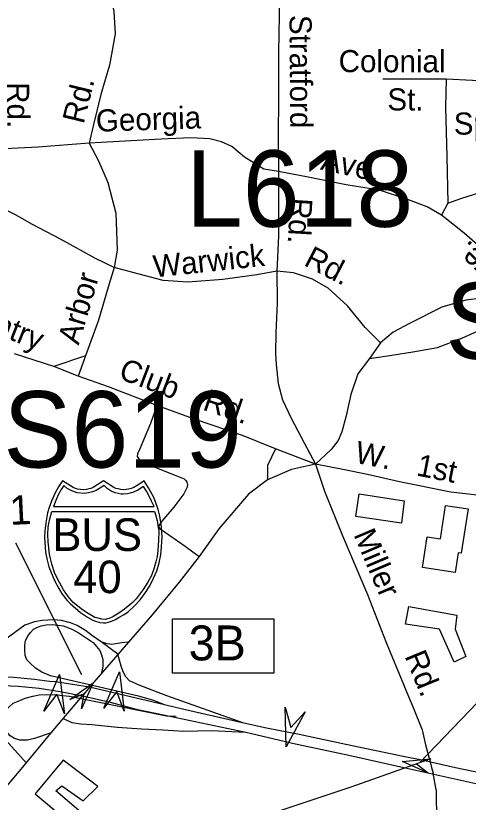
# Model space of a CAD drawing. Extents: x 1547597 to 1699558, y 810033 to 920809.
# Drawn here: x 1621816 to 1623759, y 855063 to 858442 of the extents above; entities that cross this region are included whole.
import ezdxf

# ---------------------------------------------------------------- set-up
doc = ezdxf.new("R2010")
doc.units = 0
for name, color, linetype in [('Exist Cultural Warehouse Building Footprint', 7, 'Continuous'), ('Exist Railroad Mainline', 7, 'Continuous'), ('Exist Road Non-System Type 51', 7, 'Continuous'), ('Exist Road Non-System Type 51 Label', 7, 'Continuous'), ('Exist Road Primary Interstate Divided Center Attributed', 7, 'Continuous'), ('Exist Road Primary Interstate Interchange CELL', 7, 'Continuous'), ('Exist Road Primary Interstate Ramp 1 Lane Attributed', 7, 'Continuous'), ('Exist Road Primary Interstate Shield CELL', 7, 'Continuous'), ('Exist Road Primary Interstate Shield Number Label', 7, 'Continuous'), ('Exist Road Primary Interstate Structure Cantilever Sign Attributed CELL', 7, 'Continuous'), ('Exist Road Primary Interstate Structure Cantilever Sign Number Label', 7, 'Continuous'), ('Exist Road Primary Interstate Structure Ovrhead Sign Attributed CELL', 7, 'Continuous'), ('Exist Road Primary Interstate Structure Ovrhead Sign Number Label', 7, 'Continuous'), ('Exist Road Primary US Mileage Hundredths English Label', 7, 'Continuous'), ('Exist Road Primary US UnDivided 4 Lane Attributed', 7, 'Continuous'), ('Exist Road Secondary Structure Standard Bridge Attributed CELL', 7, 'Continuous')]:
    doc.layers.add(name, color=color, linetype=linetype)

msp = doc.modelspace()

# ---------------------------------------------------------------- linework, layer by layer
at = {"layer": 'Exist Cultural Warehouse Building Footprint'}
for points in [[(1623291.3, 856387.8), (1623484.1, 856357.9), (1623472.5, 856261.4), (1623276.3, 856291.3)], [(1623562.8, 856071.5), (1623583, 856203), (1623640, 856194.3), (1623662.2, 856338.6), (1623758.4, 856323.8), (1623729.1, 856133.1), (1623716.3, 856135.1), (1623703.2, 856049.9)], [(1623504.1, 855903.6), (1623710.3, 855867), (1623703.6, 855807.1), (1623748.5, 855688.9), (1623698.6, 855665.6), (1623635.4, 855807.1), (1623489.1, 855828.7)], [(1622020.2, 855244.5), (1621899, 855099), (1622060.6, 854964.2), (1622106.4, 855012.7), (1621987.9, 855112.4), (1622014.8, 855134), (1622106.4, 855069.3), (1622168.4, 855131.3)]]:
    msp.add_lwpolyline(points, close=True, dxfattribs=at)
at = {"layer": 'Exist Railroad Mainline'}
msp.add_lwpolyline([(1620826, 854318.2), (1621032.6, 854389.6), (1621343.6, 854489.6), (1621650.5, 854595.6), (1621961.6, 854699.6), (1622242.6, 854798.1), (1622615.9, 854910.1), (1622951.9, 855027.5), (1623255.9, 855128.9), (1623550.6, 855233.7), (1623868.5, 855565)], dxfattribs=at)
at = {"layer": 'Exist Road Non-System Type 51'}
for p, q in [((1623664.2, 858169), (1623392.5, 858169.5)), ((1623671.5, 857637.1), (1623644.6, 857585.6)), ((1623381.7, 857036.3), (1623334.7, 856969)), ((1621979.5, 856935.1), (1621810.7, 856989.7)), ((1622115.7, 856981.1), (1621979.5, 856935.1)), ((1622115.7, 856981.1), (1622084.7, 856893.3)), ((1622084.7, 856893.3), (1621979.5, 856935.1)), ((1623103.4, 856515), (1622930.9, 856581.8)), ((1623576.2, 855309.2), (1623595.4, 855236.4)), ((1623595.4, 855236.4), (1623601.9, 855212.1)), ((1623601.9, 855212.1), (1623608.7, 855187.8)), ((1623621.7, 855116.1), (1623608.7, 855187.8))]:
    msp.add_line(p, q, dxfattribs=at)
for points in [[(1622050.9, 858904.9), (1622070.8, 858831.1), (1622127.5, 858744.3), (1622187.6, 858631.4), (1622218.4, 858550.9), (1622237, 858460.7), (1622243.6, 858364.7), (1622219.5, 858229.1), (1622181.7, 858103.8), (1622149.7, 857974.4), (1622131.5, 857894.3)], [(1622949.2, 858914.3), (1622948.7, 858762.2), (1622948.9, 858526.5), (1622944.8, 858284.6), (1622943.8, 858096.7), (1622942.8, 857918.9), (1622944.4, 857772.9)], [(1623664.2, 858169), (1623662.2, 858049.2), (1623666.7, 857837.1), (1623671.5, 857637.1)], [(1623871.7, 858157.6), (1623778, 858163.1), (1623664.2, 858169)], [(1622131.5, 857894.3), (1621912.6, 857877.9), (1621739.5, 857868.2)], [(1622944.4, 857772.9), (1622882, 857783.4), (1622799, 857834.7), (1622743.7, 857879.5), (1622700.1, 857900.2), (1622650.3, 857913), (1622568.4, 857918.1), (1622440.6, 857912), (1622286.5, 857902.4), (1622131.5, 857894.3)], [(1622131.5, 857894.3), (1622171.3, 857818.1), (1622211.9, 857725.6), (1622245.8, 857593.2), (1622251.4, 857435.2), (1622239.3, 857361)], [(1622944.4, 857772.9), (1622945, 857682.9), (1622943.8, 857497), (1622937.3, 857345.3)], [(1623644.6, 857585.6), (1623583.3, 857620.5), (1623491.9, 857656), (1623378.6, 857691.9), (1623235.2, 857716.2), (1623071.8, 857748.8), (1622944.4, 857772.9)], [(1623671.5, 857637.1), (1623731.7, 857658.1), (1623882.4, 857705.7), (1624040.7, 857737.1), (1624172.8, 857750.8), (1624268.7, 857753.3), (1624390.5, 857749.4), (1624568.2, 857736.4), (1624805.6, 857724.6), (1624991.1, 857701.6)], [(1622239.3, 857361), (1622159, 857398.7), (1622008.4, 857482.8), (1621885.5, 857546.5), (1621818.2, 857585.5), (1621723.9, 857630.6)], [(1623956.4, 857232.7), (1623931.6, 857303.1), (1623865.1, 857388.1), (1623798.3, 857457.3), (1623741.3, 857508), (1623644.6, 857585.6)], [(1622239.3, 857361), (1622213.2, 857275.9), (1622171.1, 857134.5), (1622115.7, 856981.1)], [(1622937.3, 857345.3), (1622851.2, 857328.2), (1622705.1, 857308.5), (1622555, 857296.8), (1622449.3, 857304.3), (1622345.8, 857331.8), (1622239.3, 857361)], [(1622937.3, 857345.3), (1622939.2, 857207.3), (1622933, 857081.4), (1622931.6, 856991.6), (1622934.8, 856943.5), (1622943.3, 856861.5), (1622962.1, 856791.2), (1622999, 856712.7), (1623055.1, 856607.7), (1623103.4, 856515)], [(1623381.7, 857036.3), (1623317, 857103.2), (1623240.5, 857196.4), (1623158, 857271.7), (1623090.5, 857310.7), (1623009.2, 857338), (1622937.3, 857345.3)], [(1623956.4, 857232.7), (1623854.6, 857232.4), (1623748.4, 857220.1), (1623646, 857189.8), (1623507.1, 857120.2), (1623436.5, 857083.2), (1623381.7, 857036.3)], [(1623334.7, 856969), (1623430.9, 856983.4), (1623521, 856998), (1623627.2, 857016.3), (1623731.7, 857056.4), (1623812.3, 857093.2), (1623892.4, 857103.8), (1623968.3, 857100.6)], [(1623334.7, 856969), (1623285.8, 856903.7), (1623254.4, 856814.3), (1623234.7, 856722.7), (1623215.7, 856655), (1623201.1, 856617.3), (1623170.5, 856577.9), (1623103.4, 856515)], [(1622422.4, 856768), (1622213.9, 856847.2), (1622084.7, 856893.3)], [(1622422.4, 856768), (1622394.6, 856690.5), (1622348.7, 856581.4), (1622338.7, 856559.6), (1622337.3, 856548.8), (1622346.6, 856535.6), (1622377.9, 856516.9), (1622497.1, 856469.1), (1622538.8, 856452.6), (1622546.7, 856445.5), (1622550.6, 856438.4), (1622553.5, 856427.3), (1622552.3, 856416.3), (1622537.9, 856388.6), (1622495, 856331.3), (1622444.1, 856270.1), (1622431.9, 856253.9), (1622429.8, 856246.3), (1622434.3, 856239.8), (1622445.5, 856232), (1622544.4, 856162.6), (1622603.8, 856118.2)], [(1622930.9, 856581.8), (1622789.9, 856638.1), (1622583.3, 856709.3), (1622422.4, 856768)], [(1622930.9, 856581.8), (1622897.2, 856509.8), (1622897.2, 856448)], [(1623103.4, 856515), (1623000, 856493.3), (1622897.2, 856448)], [(1623948.2, 856365.4), (1623860.4, 856374.8), (1623684.9, 856395.6), (1623463.9, 856439.3), (1623326.6, 856471.5), (1623221, 856493), (1623103.4, 856515)], [(1623103.4, 856515), (1623141.5, 856399.6), (1623220.4, 856204.5), (1623326.6, 855955), (1623407.3, 855750), (1623482.9, 855566.3), (1623495.9, 855534.7), (1623522.2, 855470.2), (1623561.5, 855373.9), (1623576.2, 855309.2)], [(1622897.2, 856448), (1622815, 856386.3), (1622687.6, 856238.3), (1622603.8, 856118.2)], [(1622603.8, 856118.2), (1622517.3, 856008.2), (1622402.6, 855867.7), (1622132.4, 855557.4)], [(1623621.7, 855116.1), (1623623, 854978.3), (1623624.1, 854864.3), (1623627, 854549.7)]]:
    msp.add_lwpolyline(points, dxfattribs=at)
at = {"layer": 'Exist Road Primary Interstate Divided Center Attributed'}
for points in [[(1622132.4, 855557.4), (1621987.3, 855580.3), (1621960.5, 855582.2), (1621896.7, 855589.9), (1621808.5, 855598.5), (1621707.9, 855603.2), (1621647.1, 855603.2), (1621486.4, 855593.6), (1621344.4, 855579.5)], [(1621094.5, 855465.5), (1621166.7, 855490.4), (1621252.9, 855513.8), (1621365.3, 855539.8), (1621462.3, 855555.5), (1621537.3, 855561.1), (1621639.9, 855567.2), (1621727.6, 855565.8), (1621826, 855561.8), (1621916.9, 855552.9), (1622007.3, 855538.9), (1622102.8, 855519.9)], [(1622796.2, 855402.7), (1622532.6, 855463.7), (1622454.4, 855481), (1622132.4, 855557.4)], [(1622102.8, 855519.9), (1622221.4, 855492.6), (1622334, 855462.8), (1622450.9, 855439.4), (1622804.5, 855363.8)], [(1623560, 855243.5), (1623480.4, 855259.4), (1623233.1, 855310.6), (1623032.6, 855354.7), (1622892.8, 855382), (1622796.2, 855402.7)], [(1622804.5, 855363.8), (1622829, 855358.6), (1623018.1, 855314), (1623246.3, 855265.4), (1623483.3, 855212.3)], [(1624233.7, 855069.8), (1623946.4, 855160.9), (1623703.8, 855211.6), (1623560, 855243.5)], [(1623483.3, 855212.3), (1623830.2, 855134.7), (1623968.5, 855100.4)]]:
    msp.add_lwpolyline(points, dxfattribs=at)
at = {"layer": 'Exist Road Primary Interstate Interchange CELL'}
msp.add_lwpolyline([(1622489.2, 855851), (1622924.1, 855851), (1622924.1, 855617.7), (1622489.2, 855617.7)], close=True, dxfattribs=at)
at = {"layer": 'Exist Road Primary Interstate Ramp 1 Lane Attributed'}
msp.add_line((1622254.6, 855699.5), (1622183.1, 855752.6), dxfattribs=at)
for points in [[(1622183.1, 855752.6), (1622141.3, 855780.4), (1622116, 855800.8), (1622080.4, 855822.8), (1622051.8, 855834.1), (1622012.9, 855844.4), (1621978.3, 855847.3), (1621930.3, 855844.6), (1621896.1, 855838.3), (1621855.7, 855824.3), (1621769.8, 855760.7), (1621691.6, 855697.6), (1621574, 855639), (1621508, 855616.5), (1621344.4, 855579.5)], [(1622454.4, 855481), (1622408.9, 855500.7), (1622343.3, 855518.9), (1621965.6, 855606.8), (1621928.1, 855622.3), (1621900.9, 855638.7), (1621876.6, 855662.6), (1621863.9, 855675.2), (1621856.9, 855693.5), (1621854.6, 855718.8), (1621854.6, 855738), (1621858.8, 855758.6), (1621868.6, 855777.1), (1621879.4, 855792.6), (1621892.5, 855806.7), (1621906.1, 855814.2), (1621925.3, 855821.2), (1621947.3, 855825.9), (1621974.5, 855827.3), (1621997.5, 855824.5), (1622020, 855820.7), (1622054.4, 855808.5), (1622084.4, 855792.8), (1622148.5, 855750), (1622177, 855715.7), (1622185.1, 855697.1), (1622189.9, 855675.8), (1622189.8, 855646.5), (1622184.2, 855618.7)], [(1622299.5, 855750.5), (1622272.3, 855748), (1622229.5, 855740.4), (1622208.5, 855744), (1622183.1, 855752.6)], [(1622796.2, 855402.7), (1622464.9, 855520.2), (1622346.3, 855565.8), (1622305, 855584.4), (1622289.3, 855602.2), (1622277.2, 855623.6), (1622268.7, 855647.9), (1622254.6, 855699.5)], [(1621094.5, 855465.5), (1621118.4, 855461.8), (1621178.4, 855478.2), (1621295.1, 855509.3), (1621384.1, 855524.8), (1621438.4, 855533.2), (1621489.5, 855536.5), (1621529.8, 855531.8), (1621566.8, 855525.3), (1621588.9, 855520.1), (1621610.9, 855510.7), (1621642.3, 855492.9), (1621719.3, 855390.2), (1621787.2, 855315.3), (1621862.1, 855230.4)], [(1621968.9, 855361), (1621897.1, 855336.4), (1621866.7, 855329.4), (1621834, 855329.4), (1621810.6, 855336.4), (1621791.9, 855348.1), (1621775.5, 855369.2), (1621766.1, 855392.6), (1621763.8, 855416), (1621766.1, 855439.4), (1621773.1, 855458.1), (1621787.2, 855472.1), (1621805.9, 855488.5), (1621834, 855500.2), (1621856.9, 855510.5), (1621890.2, 855519.4), (1621917.3, 855524.6), (1621948.6, 855526), (1621991.9, 855524.6), (1622047.6, 855518.5), (1622463.7, 855433.9), (1622505.4, 855432.5)], [(1622022.8, 855421.4), (1622057.1, 855405.8), (1622096, 855399.6), (1622142.7, 855397.3), (1622252.6, 855385.5), (1622355.6, 855378.5), (1622449.2, 855373.8), (1622538.1, 855369.2), (1622655.1, 855371.5), (1622804.5, 855363.8)]]:
    msp.add_lwpolyline(points, dxfattribs=at)
at = {"layer": 'Exist Road Primary Interstate Shield CELL'}
for points in [[(1622192.9, 855833.7), (1622202.4, 855834.6), (1622215.1, 855837.1), (1622227.5, 855841.2), (1622241.6, 855847.4), (1622262.5, 855859), (1622279.2, 855868.8), (1622298.6, 855881.8), (1622324.7, 855905.5), (1622350.7, 855932.9), (1622373.7, 855963.9), (1622392, 855992.9), (1622408, 856026.1), (1622421.5, 856057), (1622432.1, 856092.3), (1622439.2, 856126.6), (1622442.8, 856162.3), (1622445.1, 856201.8), (1622442.5, 856246.4), (1622434.7, 856291.9), (1622427.4, 856320.3), (1622416.4, 856354.2), (1622407.4, 856375.9), (1622386.6, 856414.3), (1622367.8, 856443.9), (1622340.6, 856424.8), (1622322.8, 856415.3), (1622312, 856410.5), (1622300.8, 856408.3), (1622280.3, 856405.8), (1622267.5, 856406.4), (1622255.5, 856409.1), (1622245.4, 856411.3), (1622237.1, 856415.3), (1622192.9, 856443.9), (1622148.6, 856415.3), (1622139.3, 856411.1), (1622129.8, 856409.1), (1622120.7, 856406.6), (1622105.6, 856405.8), (1622094, 856406.2), (1622082.1, 856408.3), (1622072.7, 856410.3), (1622062.2, 856415.3), (1622017.1, 856443.9), (1621999.4, 856418.2), (1621984.9, 856392.8), (1621969.6, 856356.9), (1621960, 856329.1), (1621953.2, 856306.2), (1621944.9, 856264.2), (1621940.5, 856227.7), (1621939.8, 856201.8), (1621944.5, 856137.3), (1621951.6, 856103), (1621958.8, 856075.2), (1621982.7, 856015.1), (1622000.6, 855981.5), (1622016, 855957.4), (1622037.6, 855930.2), (1622049.3, 855917.2), (1622094.1, 855878.1), (1622124, 855857.6), (1622147.9, 855844.7), (1622159.2, 855840.4), (1622176.7, 855835.5)], [(1622022.5, 856423.2), (1622011.5, 856406.3), (1621998.8, 856383.4), (1621988.7, 856359.8), (1621978.3, 856333.6), (1622409.9, 856333.5), (1622399.8, 856355.9), (1622389.1, 856378.4), (1622377.8, 856399), (1622364.1, 856418.9), (1622339.9, 856403.6), (1622322.3, 856395.3), (1622308.1, 856390.4), (1622296.1, 856387.7), (1622277.5, 856386.2), (1622269.2, 856386.7), (1622243.3, 856392.6), (1622225.7, 856399.8), (1622209, 856410.9), (1622195.5, 856423.6), (1622161.3, 856403), (1622146.1, 856396.3), (1622128.7, 856391.8), (1622109.6, 856389.4), (1622080.2, 856392.6), (1622057.1, 856400.6), (1622037.2, 856410.9)], [(1622412.4, 856312.2), (1622417, 856300), (1622423.4, 856272.9), (1622426.7, 856252.1), (1622430.2, 856228.1), (1622429, 856187), (1622427, 856144.4), (1622423.1, 856119.2), (1622417.8, 856096.2), (1622410.7, 856070.8), (1622399.2, 856036.9), (1622383.2, 856008.3), (1622363.4, 855976.5), (1622341.9, 855948.6), (1622332.6, 855937), (1622314.8, 855918.4), (1622282.6, 855892.5), (1622259.1, 855874.9), (1622230.9, 855858.3), (1622216.6, 855851.9), (1622200, 855848.4), (1622186.3, 855849.4), (1622169.6, 855853.8), (1622156.2, 855857.5), (1622126.8, 855873.4), (1622102.9, 855889.3), (1622063.1, 855921.9), (1622041.7, 855947.1), (1622021.6, 855976.4), (1622003.8, 856006.5), (1621984.7, 856046.2), (1621971.2, 856086.1), (1621961.4, 856129.2), (1621954.8, 856181.8), (1621954.1, 856213.9), (1621956.1, 856244.7), (1621959, 856260.9), (1621962.9, 856281), (1621970.8, 856311.9)]]:
    msp.add_lwpolyline(points, close=True, dxfattribs=at)
at = {"layer": 'Exist Road Primary Interstate Structure Cantilever Sign Attributed CELL'}
for points in [[(1621937.4, 855454.8), (1622003.6, 855612.2), (1622025, 855442.8), (1621992, 855527.6)], [(1623058.7, 855451.2), (1622977.1, 855301.2), (1622972.7, 855471.9), (1622997.1, 855384.2)]]:
    msp.add_lwpolyline(points, close=True, dxfattribs=at)
at = {"layer": 'Exist Road Primary Interstate Structure Ovrhead Sign Attributed CELL'}
msp.add_lwpolyline([(1622194.5, 855467.3), (1622262.4, 855624), (1622281.9, 855454.4), (1622249.9, 855539.5)], close=True, dxfattribs=at)
at = {"layer": 'Exist Road Primary US Mileage Hundredths English Label'}
msp.add_line((1622099.5, 855610.9), (1621817, 856175.9), dxfattribs=at)
at = {"layer": 'Exist Road Primary US UnDivided 4 Lane Attributed'}
for points in [[(1622132.4, 855557.4), (1622102.8, 855519.9)], [(1621761.7, 855114), (1621839.6, 855205.9), (1621968.9, 855361), (1622102.8, 855519.9)]]:
    msp.add_lwpolyline(points, dxfattribs=at)
at = {"layer": 'Exist Road Secondary Structure Standard Bridge Attributed CELL'}
for points in [[(1622049.2, 855504.8), (1622148.1, 855576.1), (1622098.1, 855464.9), (1622109.6, 855528.8)], [(1623588, 855187.7), (1623476.7, 855237.6), (1623598, 855250), (1623536.9, 855227.9)]]:
    msp.add_lwpolyline(points, close=True, dxfattribs=at)

# ---------------------------------------------------------------- texts
at = {"layer": 'Exist Road Non-System Type 51 Label'}
for s, rotation, p in [('Stratford', 270.4123, (1622991.6, 858445.2)), ('Colonial', 359.8928, (1623202.6, 858199.6)), ('Rd.', 270.3705, (1621778.8, 858156.3)), ('Rd.', 76.0951, (1622107.6, 857973.3)), ('St.', 359.8928, (1623411.8, 858035)), ('Georgia', 1.8623, (1622161.8, 857943.5)), ('Springdale', 0.267, (1623697.3, 857931)), ('Ave.', 347.6767, (1623121.5, 857781.8)), ('Rd.', 266.4644, (1622995.9, 857661.9)), ('Warwick', 6.0177, (1622411.4, 857317.4)), ('Rd.', 332.5015, (1623048.7, 857372)), ('Ave.', 135.2696, (1623938.6, 857304.4)), ('Arbor', 73.4266, (1622086.4, 857024.2)), ('Country', 338.0803, (1621500.3, 857167.5)), ('Club', 339.1836, (1622253.1, 856885)), ('Rd.', 340.9828, (1622614.4, 856750.6)), ('W.', 348.8144, (1623268.4, 856522.5)), ('1st', 348.8144, (1623532.7, 856467.5)), ('Miller', 293.0573, (1623265.4, 856213.3)), ('Rd.', 292.3845, (1623484.6, 855691.5))]:
    msp.add_text(s, height=95, rotation=rotation, dxfattribs=at).set_placement(p)
at = {"layer": 'Exist Road Primary Interstate Interchange CELL'}
msp.add_text('3B', height=150, dxfattribs=at).set_placement((1622558.7, 855672.6))
at = {"layer": 'Exist Road Primary Interstate Shield Number Label'}
for s, p in [('BUS', (1621973.5, 856142.7)), ('40', (1622062.9, 855961.4))]:
    msp.add_text(s, height=140, dxfattribs=at).set_placement(p)
at = {"layer": 'Exist Road Primary Interstate Structure Cantilever Sign Number Label'}
msp.add_text('L618', height=328.08, dxfattribs=at).set_placement((1622546.9, 857535.3))
at = {"layer": 'Exist Road Primary Interstate Structure Ovrhead Sign Number Label'}
for s, p in [('S616', (1623660.9, 856967.4)), ('S619', (1621763, 856501.1))]:
    msp.add_text(s, height=328.08, dxfattribs=at).set_placement(p)
at = {"layer": 'Exist Road Primary US Mileage Hundredths English Label'}
msp.add_text('.01', height=125, rotation=2.7889, dxfattribs=at).set_placement((1621653.4, 856247.5))

doc.saveas('drawing.dxf')
